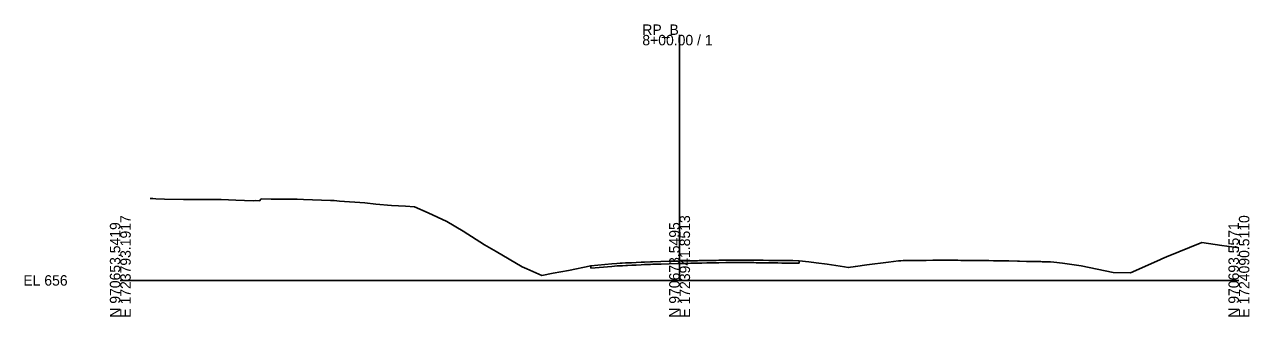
# Model space of a CAD drawing. Extents: x -26 to 1723826, y -10 to 971808.
# Drawn here: x 1274.3 to 1602.8, y -9.7 to 68.7 of the extents above; entities that cross this region are included whole.
import ezdxf

# ---------------------------------------------------------------- set-up
doc = ezdxf.new("R2010")
doc.units = 0
for name, color, linetype in [('Exist Cross Section Cell', 7, 'Continuous'), ('Exist XS Center Line Elevation Label', 7, 'Continuous'), ('Exist XS Ground Line', 7, 'Continuous')]:
    doc.layers.add(name, color=color, linetype=linetype)

msp = doc.modelspace()

# ---------------------------------------------------------------- linework, layer by layer
at = {"layer": 'Exist Cross Section Cell'}
for p, q in [((1450, 0), (1450, 65.88)), ((1300, 0), (1450, 0)), ((1450, 0), (1600, 0))]:
    msp.add_line(p, q, dxfattribs=at)
at = {"layer": 'Exist XS Ground Line'}
for p, q in [((1426.16, 3.92), (1426.16, 3.25)), ((1482.03, 5.28), (1482.03, 4.62))]:
    msp.add_line(p, q, dxfattribs=at)
for points in [[(1307.99, 21.96), (1308.69, 21.94), (1309.54, 21.92), (1311.89, 21.82), (1316.97, 21.67), (1320.78, 21.67), (1327.06, 21.68), (1330.99, 21.53), (1335.63, 21.35), (1336.24, 21.41), (1337.37, 21.39), (1337.79, 21.89), (1340.43, 21.83), (1341.29, 21.8), (1343.78, 21.8), (1347.46, 21.82), (1349.11, 21.75), (1356.35, 21.46), (1357.33, 21.41), (1358.78, 21.28), (1365.57, 20.77), (1368.52, 20.42), (1372.71, 20.14), (1376.45, 19.95), (1378.91, 19.78), (1382.6, 18.14), (1387.6, 15.79), (1391.92, 13.2), (1397.68, 9.54), (1400.82, 7.71), (1407.77, 3.66), (1409, 3.12), (1413.09, 1.32), (1416.08, 1.94), (1420.2, 2.68), (1426.16, 3.92), (1431.79, 4.41), (1433.18, 4.54), (1434.1, 4.58), (1434.6, 4.61), (1435.53, 4.67), (1436.02, 4.7), (1437.12, 4.74), (1438.32, 4.8), (1439.65, 4.86), (1440.55, 4.9), (1442.17, 4.96), (1442.77, 4.98), (1445, 5.06), (1447.22, 5.12), (1450.06, 5.19), (1452.25, 5.23), (1452.99, 5.25), (1454.77, 5.29), (1455.27, 5.3), (1455.95, 5.32), (1457.32, 5.34), (1458.88, 5.36), (1459.82, 5.37), (1460.54, 5.39), (1462.37, 5.43), (1462.81, 5.43), (1464.88, 5.44), (1465.96, 5.45), (1467.48, 5.46), (1467.97, 5.45), (1469.29, 5.43), (1469.91, 5.43), (1470.52, 5.42), (1472.42, 5.4), (1473.89, 5.38), (1474.95, 5.37), (1476.33, 5.35), (1477.47, 5.33), (1479.77, 5.31), (1480.35, 5.3), (1482.03, 5.28), (1484.67, 4.95), (1486.6, 4.71), (1489.6, 4.33), (1494.2, 3.61), (1495.25, 3.42), (1497.16, 3.74), (1500.22, 4.19), (1505.99, 4.91), (1508.67, 5.26), (1509.31, 5.27), (1509.99, 5.3), (1511.7, 5.31), (1512.8, 5.32), (1514.24, 5.35), (1515.32, 5.37), (1516.14, 5.38), (1517.87, 5.39), (1520.38, 5.42), (1520.72, 5.42), (1522.72, 5.43), (1524.66, 5.39), (1525.42, 5.38), (1525.93, 5.37), (1527.93, 5.36), (1529.46, 5.34), (1530.45, 5.33), (1531.73, 5.31), (1532.96, 5.3), (1534.16, 5.28), (1534.61, 5.28), (1535.5, 5.26), (1537.58, 5.23), (1538.02, 5.22), (1538.34, 5.21), (1540.62, 5.16), (1541.13, 5.15), (1543.07, 5.1), (1545.04, 5.07), (1545.6, 5.06), (1546.61, 5.04), (1546.91, 5.03), (1547.25, 5.02), (1548.11, 4.99), (1548.88, 4.96), (1549.47, 4.94), (1550.34, 4.85), (1552.67, 4.59), (1557.66, 3.94), (1566.31, 2.15), (1570.94, 2.04), (1578.81, 5.56), (1579.3, 5.78), (1580.56, 6.28), (1590.1, 10.14), (1595.44, 9.39), (1599.48, 8.79), (1600, 8.73)], [(1426.16, 3.25), (1431.85, 3.74), (1433.23, 3.87), (1434.13, 3.92), (1434.64, 3.95), (1435.57, 4), (1436.05, 4.03), (1437.15, 4.08), (1438.34, 4.13), (1439.68, 4.19), (1440.58, 4.23), (1442.19, 4.3), (1442.79, 4.32), (1445.02, 4.39), (1447.24, 4.45), (1450.07, 4.52), (1452.27, 4.57), (1453.01, 4.58), (1454.79, 4.62), (1455.29, 4.64), (1455.96, 4.65), (1457.33, 4.67), (1458.88, 4.69), (1459.83, 4.71), (1460.55, 4.72), (1462.38, 4.76), (1462.81, 4.76), (1464.88, 4.77), (1465.97, 4.78), (1467.47, 4.79), (1467.96, 4.78), (1469.28, 4.77), (1469.9, 4.76), (1470.51, 4.75), (1472.41, 4.73), (1473.88, 4.72), (1474.94, 4.71), (1476.32, 4.68), (1477.46, 4.66), (1479.77, 4.64), (1480.34, 4.64), (1482.03, 4.62)]]:
    msp.add_lwpolyline(points, dxfattribs=at)

# ---------------------------------------------------------------- texts
at = {"layer": 'Exist Cross Section Cell'}
for s, p in [('8+00.00 / 1', (1440, 63.08)), ('RP_B', (1440, 65.88)), ('EL 656', (1274, -1.4))]:
    msp.add_text(s, height=2.8, dxfattribs=at).set_placement(p)
for s, p in [('E 1723793.1917', (1302.8, -10)), ('E 1723941.8513', (1452.8, -10)), ('E 1724090.5110', (1602.8, -10)), ('N 970653.5419', (1300, -10)), ('N 970673.5495', (1450, -10)), ('N 970693.5571', (1600, -10))]:
    msp.add_text(s, height=2.8, rotation=90, dxfattribs=at).set_placement(p)
at = {"layer": 'Exist XS Center Line Elevation Label'}
msp.add_text('661.19', height=0.18, dxfattribs=at).set_placement((1449.66, 1.1))
msp.add_text('661.19', height=0.18, dxfattribs=at).set_placement((1449.66, 1.1))
msp.add_text('661.19', height=0.18, dxfattribs=at).set_placement((1449.66, 1.1))

doc.saveas('drawing.dxf')
